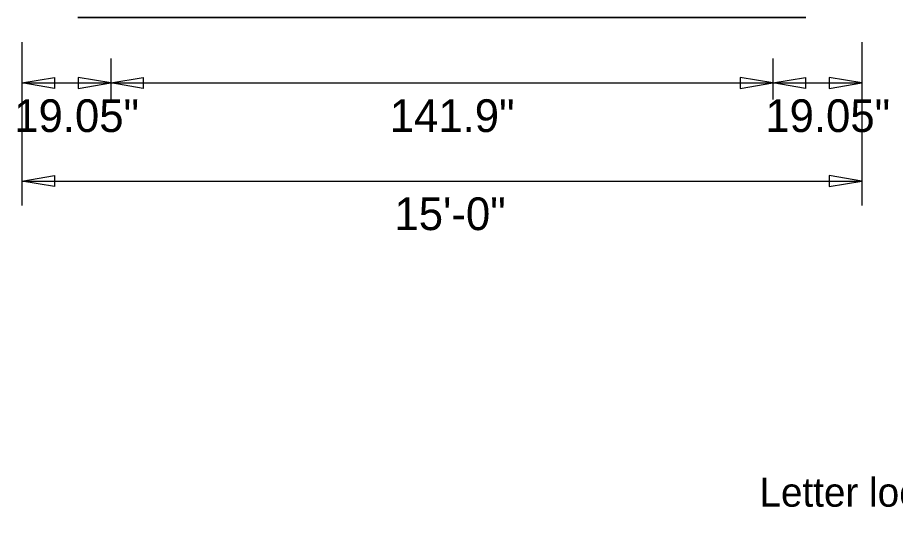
# Model space of a CAD drawing. Extents: x 2149934 to 2150188, y 145113 to 145238.
# Drawn here: x 2149961.32 to 2149977, y 145187.81 to 145196.69 of the extents above; entities that cross this region are included whole.
import ezdxf

# ---------------------------------------------------------------- set-up
doc = ezdxf.new("R2010")
doc.units = 0
for name, color, linetype in [('GSBWFILL', 7, 'Continuous'), ('GSCOLORFILL', 7, 'Continuous'), ('GSDIMS', 7, 'Continuous'), ('GSOUTLINE', 7, 'Continuous'), ('Level 1', 7, 'Continuous')]:
    doc.layers.add(name, color=color, linetype=linetype)

msp = doc.modelspace()

# ---------------------------------------------------------------- linework, layer by layer
at = {"layer": 'GSBWFILL'}
for p, q in [((2149975.395, 145196.695), (2149962.395, 145196.695)), ((2149962.395, 145196.695), (2149975.395, 145196.695))]:
    msp.add_line(p, q, dxfattribs=at)
at = {"layer": 'GSCOLORFILL'}
for p, q in [((2149962.395, 145196.695), (2149975.395, 145196.695)), ((2149975.395, 145196.695), (2149962.395, 145196.695)), ((2149975.395, 145196.695), (2149962.395, 145196.695))]:
    msp.add_line(p, q, dxfattribs=at)
at = {"layer": 'GSDIMS'}
for p, q in [((2149961.395, 145196.257), (2149961.395, 145193.341)), ((2149976.395, 145196.257), (2149976.395, 145193.341)), ((2149961.395, 145195.966), (2149961.395, 145195.236)), ((2149962.982, 145195.966), (2149962.982, 145195.236)), ((2149962.982, 145195.966), (2149962.982, 145195.236)), ((2149974.809, 145195.966), (2149974.809, 145195.236)), ((2149974.809, 145195.966), (2149974.809, 145195.236)), ((2149976.395, 145195.966), (2149976.395, 145195.236)), ((2149961.395, 145195.528), (2149962.982, 145195.528)), ((2149962.982, 145195.528), (2149974.809, 145195.528)), ((2149974.809, 145195.528), (2149976.395, 145195.528)), ((2149961.395, 145194.216), (2149961.395, 145193.486)), ((2149976.395, 145194.216), (2149976.395, 145193.486)), ((2149961.395, 145193.778), (2149976.395, 145193.778))]:
    msp.add_line(p, q, dxfattribs=at)
for points in [[(2149961.395, 145195.528), (2149961.979, 145195.625), (2149961.979, 145195.431)], [(2149962.982, 145195.528), (2149962.399, 145195.625), (2149962.399, 145195.431)], [(2149962.982, 145195.528), (2149963.565, 145195.625), (2149963.565, 145195.431)], [(2149974.809, 145195.528), (2149974.225, 145195.625), (2149974.225, 145195.431)], [(2149974.809, 145195.528), (2149975.392, 145195.625), (2149975.392, 145195.431)], [(2149976.395, 145195.528), (2149975.812, 145195.625), (2149975.812, 145195.431)], [(2149961.395, 145193.778), (2149961.979, 145193.875), (2149961.979, 145193.681)], [(2149976.395, 145193.778), (2149975.812, 145193.875), (2149975.812, 145193.681)]]:
    msp.add_lwpolyline(points, close=True, dxfattribs=at)
at = {"layer": 'GSOUTLINE'}
for p, q in [((2149975.395, 145196.695), (2149962.395, 145196.695)), ((2149962.395, 145196.695), (2149975.395, 145196.695))]:
    msp.add_line(p, q, dxfattribs=at)

# ---------------------------------------------------------------- texts
at = {"layer": 'GSDIMS'}
for s, p in [('19.05"', (2149961.26, 145194.653)), ('141.9"', (2149967.966, 145194.653)), ('19.05"', (2149974.673, 145194.653)), ('15\'-0"', (2149968.05, 145192.903))]:
    msp.add_text(s, height=0.5833, dxfattribs=at).set_placement(p)
at = {"layer": 'Level 1'}
msp.add_text('Letter locations are panel edge to lower left corner', height=0.51652, dxfattribs=at).set_placement((2149974.568, 145187.968))

doc.saveas('drawing.dxf')
